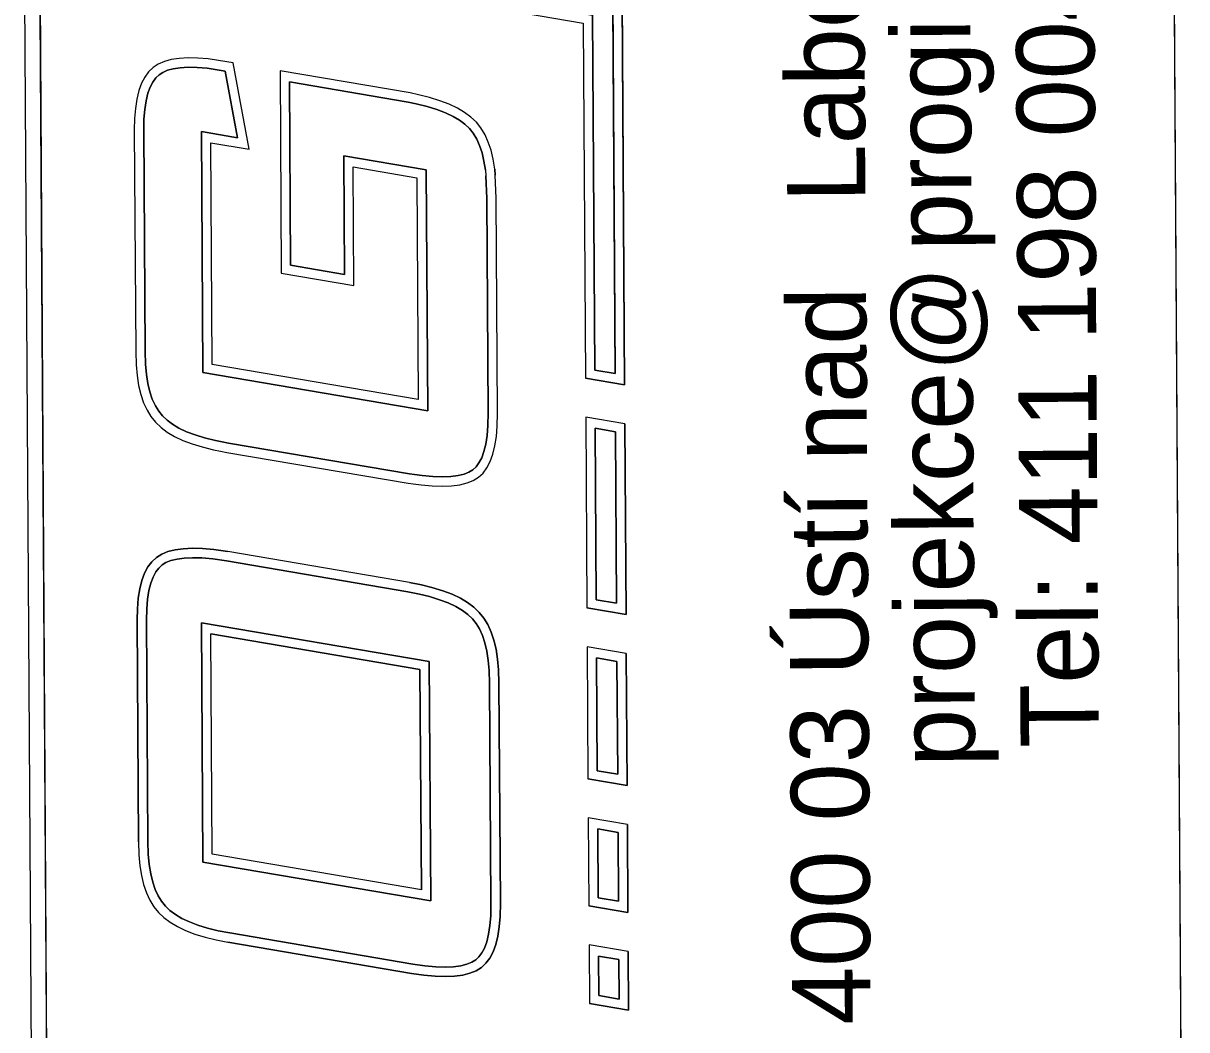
# Model space of a CAD drawing. Extents: x -735036 to -734743, y -1144813 to -1144181.
# Drawn here: x -734819.2 to -734790.93, y -1144221.87 to -1144197.41 of the extents above; entities that cross this region are included whole.
import ezdxf

# ---------------------------------------------------------------- set-up
doc = ezdxf.new("R2010")
doc.units = 0
doc.layers.add('000_rozpiska', color=7, linetype='Continuous')

# ---------------------------------------------------------------- blocks, each defined once
blk = doc.blocks.new('A$C2B726605')
at = {"layer": '000_rozpiska'}
for p, q in [((-8.894, 71.716), (-181.794, 71.716)), ((-8.894, 71.716), (-181.794, 71.716)), ((-8.894, 71.336), (-63.044, 71.336)), ((-23.113, 69), (-23.336, 68.949)), ((-22.876, 69.037), (-23.113, 69)), ((-22.611, 69.06), (-22.876, 69.037)), ((-22.293, 69.067), (-22.611, 69.06)), ((-16.9, 69.067), (-22.293, 69.067)), ((-16.631, 69.06), (-16.9, 69.067)), ((-16.382, 69.039), (-16.631, 69.06)), ((-16.158, 69.003), (-16.382, 69.039)), ((-15.946, 68.95), (-16.158, 69.003)), ((-35.366, 68.674), (-35.185, 68.734)), ((-35.185, 68.734), (-34.983, 68.781)), ((-34.983, 68.781), (-34.759, 68.816)), ((-34.759, 68.816), (-34.511, 68.836)), ((-34.511, 68.836), (-34.202, 68.844)), ((-34.202, 68.844), (-28.821, 68.844)), ((-28.821, 68.844), (-28.555, 68.837)), ((-28.555, 68.837), (-28.314, 68.816)), ((-28.314, 68.816), (-28.102, 68.782)), ((-28.102, 68.782), (-27.922, 68.735)), ((-27.922, 68.735), (-27.774, 68.68)), ((-23.875, 68.705), (-24.014, 68.594)), ((-23.718, 68.8), (-23.875, 68.705)), ((-23.536, 68.882), (-23.718, 68.8)), ((-23.336, 68.949), (-23.536, 68.882)), ((-23.274, 68.729), (-23.453, 68.67)), ((-23.07, 68.776), (-23.274, 68.729)), ((-22.849, 68.811), (-23.07, 68.776)), ((-22.599, 68.832), (-22.849, 68.811)), ((-22.29, 68.839), (-22.599, 68.832)), ((-16.903, 68.839), (-22.29, 68.839)), ((-16.644, 68.832), (-16.903, 68.839)), ((-16.41, 68.812), (-16.644, 68.832)), ((-16.203, 68.779), (-16.41, 68.812)), ((-16.014, 68.732), (-16.203, 68.779)), ((-15.868, 68.677), (-16.014, 68.732)), ((-15.774, 68.885), (-15.946, 68.95)), ((-15.623, 68.805), (-15.774, 68.885)), ((-15.494, 68.711), (-15.623, 68.805)), ((-15.389, 68.598), (-15.494, 68.711)), ((-35.877, 68.32), (-35.774, 68.43)), ((-35.774, 68.43), (-35.655, 68.523)), ((-35.655, 68.523), (-35.523, 68.603)), ((-35.523, 68.603), (-35.366, 68.674)), ((-27.774, 68.68), (-27.647, 68.612)), ((-27.647, 68.612), (-27.556, 68.541)), ((-27.556, 68.541), (-27.482, 68.458)), ((-27.482, 68.458), (-27.424, 68.363)), ((-24.14, 68.463), (-24.252, 68.312)), ((-24.014, 68.594), (-24.14, 68.463)), ((-23.86, 68.425), (-23.966, 68.315)), ((-23.744, 68.517), (-23.86, 68.425)), ((-23.612, 68.597), (-23.744, 68.517)), ((-23.453, 68.67), (-23.612, 68.597)), ((-15.744, 68.612), (-15.868, 68.677)), ((-15.646, 68.54), (-15.744, 68.612)), ((-15.57, 68.458), (-15.646, 68.54)), ((-15.513, 68.368), (-15.57, 68.458)), ((-15.31, 68.474), (-15.389, 68.598)), ((-15.247, 68.325), (-15.31, 68.474)), ((-36.072, 68.03), (-35.977, 68.188)), ((-35.977, 68.188), (-35.877, 68.32)), ((-27.424, 68.363), (-27.377, 68.245)), ((-27.377, 68.245), (-27.339, 68.093)), ((-24.358, 68.136), (-24.456, 67.934)), ((-24.252, 68.312), (-24.358, 68.136)), ((-24.062, 68.185), (-24.157, 68.028)), ((-23.966, 68.315), (-24.062, 68.185)), ((-15.462, 68.25), (-15.513, 68.368)), ((-15.425, 68.113), (-15.462, 68.25)), ((-15.201, 68.16), (-15.247, 68.325)), ((-15.174, 67.968), (-15.201, 68.16)), ((-36.24, 67.64), (-36.158, 67.849)), ((-36.158, 67.849), (-36.072, 68.03)), ((-27.339, 68.093), (-27.316, 67.921)), ((-27.316, 67.921), (-27.309, 67.715)), ((-24.456, 67.934), (-24.542, 67.709)), ((-24.247, 67.843), (-24.327, 67.634)), ((-24.157, 68.028), (-24.247, 67.843)), ((-15.401, 67.946), (-15.425, 68.113)), ((-15.39, 67.746), (-15.401, 67.946)), ((-15.161, 67.749), (-15.174, 67.968)), ((-36.313, 67.406), (-36.24, 67.64)), ((-27.309, 67.715), (-27.318, 67.49)), ((-24.542, 67.709), (-24.617, 67.47)), ((-24.327, 67.634), (-24.398, 67.408)), ((-15.396, 67.53), (-15.39, 67.746)), ((-15.168, 67.516), (-15.161, 67.749)), ((-36.377, 67.15), (-36.313, 67.406)), ((-35.686, 61.98), (-34.711, 67.51)), ((-35.414, 62.208), (-34.52, 67.282)), ((-34.711, 67.51), (-28.895, 67.51)), ((-34.52, 67.282), (-29.166, 67.282)), ((-30.06, 62.208), (-29.166, 67.282)), ((-29.869, 61.98), (-28.895, 67.51)), ((-27.318, 67.49), (-27.343, 67.228)), ((-24.617, 67.47), (-24.689, 67.189)), ((-24.398, 67.408), (-24.466, 67.138)), ((-23.773, 61.981), (-22.812, 67.436)), ((-22.812, 67.436), (-16.956, 67.436)), ((-16.956, 67.436), (-17.109, 66.562)), ((-15.455, 67.047), (-15.418, 67.292)), ((-15.418, 67.292), (-15.396, 67.53)), ((-15.192, 67.265), (-15.168, 67.516)), ((-36.434, 66.871), (-36.377, 67.15)), ((-27.343, 67.228), (-27.394, 66.891)), ((-24.723, 67.024), (-24.755, 66.868)), ((-24.689, 67.189), (-24.723, 67.024)), ((-24.466, 67.138), (-24.499, 66.978)), ((-23.501, 62.209), (-22.62, 67.208)), ((-22.62, 67.208), (-17.227, 67.208)), ((-17.227, 67.208), (-17.39, 66.281)), ((-15.489, 66.851), (-15.455, 67.047)), ((-15.293, 66.654), (-15.23, 67.01)), ((-15.23, 67.01), (-15.192, 67.265)), ((-37.443, 62.463), (-36.658, 66.917)), ((-37.218, 62.426), (-36.434, 66.871)), ((-27.394, 66.891), (-28.17, 62.485)), ((-27.946, 62.446), (-27.168, 66.857)), ((-24.755, 66.868), (-25.53, 62.465)), ((-24.531, 66.825), (-25.305, 62.43)), ((-24.499, 66.978), (-24.531, 66.825)), ((-17.109, 66.562), (-15.489, 66.851)), ((-17.39, 66.281), (-15.293, 66.654)), ((-20.41, 65.519), (-20.721, 63.755)), ((-15.492, 65.519), (-20.41, 65.519)), ((-16.049, 62.363), (-15.492, 65.519)), ((-20.219, 65.291), (-20.45, 63.983)), ((-15.764, 65.291), (-20.219, 65.291)), ((-16.272, 62.408), (-15.764, 65.291)), ((-20.45, 63.983), (-17.564, 63.983)), ((-17.564, 63.983), (-17.916, 61.981)), ((-20.721, 63.755), (-17.836, 63.755)), ((-17.836, 63.755), (-18.108, 62.209)), ((-28.168, 62.494), (-28.229, 62.211)), ((-37.262, 62.134), (-37.218, 62.426)), ((-35.414, 62.208), (-30.06, 62.208)), ((-28.229, 62.211), (-28.289, 61.967)), ((-25.547, 62.345), (-25.574, 62.154)), ((-25.53, 62.465), (-25.547, 62.345)), ((-25.321, 62.313), (-25.348, 62.126)), ((-25.305, 62.43), (-25.321, 62.313)), ((-18.108, 62.209), (-23.501, 62.209)), ((-16.383, 61.95), (-16.316, 62.214)), ((-16.316, 62.214), (-16.272, 62.408)), ((-16.095, 62.161), (-16.049, 62.363)), ((-37.288, 61.87), (-37.262, 62.134)), ((-35.686, 61.98), (-29.869, 61.98)), ((-28.289, 61.967), (-28.367, 61.72)), ((-25.574, 62.154), (-25.602, 61.884)), ((-25.348, 62.126), (-25.375, 61.868)), ((-17.916, 61.981), (-23.773, 61.981)), ((-16.456, 61.717), (-16.383, 61.95)), ((-16.163, 61.888), (-16.095, 62.161)), ((-37.298, 61.64), (-37.288, 61.87)), ((-37.291, 61.435), (-37.298, 61.64)), ((-28.367, 61.72), (-28.448, 61.51)), ((-25.602, 61.884), (-25.612, 61.64)), ((-25.612, 61.64), (-25.605, 61.413)), ((-25.375, 61.868), (-25.384, 61.64)), ((-25.384, 61.64), (-25.377, 61.431)), ((-16.537, 61.505), (-16.456, 61.717)), ((-16.328, 61.415), (-16.241, 61.642)), ((-16.241, 61.642), (-16.163, 61.888)), ((-37.268, 61.258), (-37.291, 61.435)), ((-28.448, 61.51), (-28.537, 61.326)), ((-25.605, 61.413), (-25.579, 61.21)), ((-25.377, 61.431), (-25.354, 61.252)), ((-16.626, 61.321), (-16.537, 61.505)), ((-16.426, 61.212), (-16.328, 61.415)), ((-37.231, 61.111), (-37.268, 61.258)), ((-37.184, 60.99), (-37.231, 61.111)), ((-28.63, 61.17), (-28.729, 61.038)), ((-28.537, 61.326), (-28.63, 61.17)), ((-25.579, 61.21), (-25.534, 61.032)), ((-25.354, 61.252), (-25.317, 61.102)), ((-25.317, 61.102), (-25.272, 60.989)), ((-16.816, 61.036), (-16.719, 61.167)), ((-16.719, 61.167), (-16.626, 61.321)), ((-16.53, 61.04), (-16.426, 61.212)), ((-37.126, 60.896), (-37.184, 60.99)), ((-37.055, 60.819), (-37.126, 60.896)), ((-36.959, 60.747), (-37.055, 60.819)), ((-28.949, 60.838), (-29.082, 60.76)), ((-28.835, 60.928), (-28.949, 60.838)), ((-28.729, 61.038), (-28.835, 60.928)), ((-25.534, 61.032), (-25.477, 60.887)), ((-25.477, 60.887), (-25.396, 60.755)), ((-25.272, 60.989), (-25.213, 60.893)), ((-25.213, 60.893), (-25.141, 60.813)), ((-25.141, 60.813), (-25.047, 60.744)), ((-17.18, 60.751), (-17.039, 60.833)), ((-17.039, 60.833), (-16.924, 60.924)), ((-16.924, 60.924), (-16.816, 61.036)), ((-16.771, 60.755), (-16.642, 60.889)), ((-16.642, 60.889), (-16.53, 61.04)), ((-36.839, 60.683), (-36.959, 60.747)), ((-36.687, 60.627), (-36.839, 60.683)), ((-36.506, 60.581), (-36.687, 60.627)), ((-36.295, 60.547), (-36.506, 60.581)), ((-36.059, 60.526), (-36.295, 60.547)), ((-35.746, 60.519), (-36.059, 60.526)), ((-30.401, 60.519), (-35.746, 60.519)), ((-30.095, 60.527), (-30.401, 60.519)), ((-29.849, 60.547), (-30.095, 60.527)), ((-29.624, 60.582), (-29.849, 60.547)), ((-29.421, 60.629), (-29.624, 60.582)), ((-29.242, 60.688), (-29.421, 60.629)), ((-29.082, 60.76), (-29.242, 60.688)), ((-25.396, 60.755), (-25.295, 60.643)), ((-25.295, 60.643), (-25.168, 60.55)), ((-25.168, 60.55), (-25.016, 60.469)), ((-25.047, 60.744), (-24.922, 60.677)), ((-24.922, 60.677), (-24.774, 60.621)), ((-24.774, 60.621), (-24.592, 60.576)), ((-24.592, 60.576), (-24.381, 60.543)), ((-24.381, 60.543), (-24.143, 60.522)), ((-24.143, 60.522), (-23.837, 60.515)), ((-23.837, 60.515), (-18.622, 60.515)), ((-18.622, 60.515), (-18.073, 60.532)), ((-17.938, 60.543), (-18.073, 60.532)), ((-17.938, 60.543), (-17.714, 60.577)), ((-17.714, 60.577), (-17.514, 60.623)), ((-17.514, 60.623), (-17.334, 60.683)), ((-17.334, 60.683), (-17.18, 60.751)), ((-17.252, 60.47), (-17.076, 60.547)), ((-17.076, 60.547), (-16.91, 60.645)), ((-16.91, 60.645), (-16.771, 60.755)), ((-25.016, 60.469), (-24.842, 60.403)), ((-24.842, 60.403), (-24.638, 60.353)), ((-24.638, 60.353), (-24.409, 60.316)), ((-24.409, 60.316), (-24.156, 60.295)), ((-24.156, 60.295), (-23.84, 60.287)), ((-23.84, 60.287), (-18.618, 60.287)), ((-18.618, 60.287), (-18.06, 60.305)), ((-17.912, 60.316), (-18.06, 60.305)), ((-17.912, 60.316), (-17.671, 60.353)), ((-17.671, 60.353), (-17.453, 60.403)), ((-17.453, 60.403), (-17.252, 60.47)), ((-38.371, 57.193), (-38.204, 58.143)), ((-36.779, 58.143), (-38.204, 58.143)), ((-36.946, 57.193), (-36.779, 58.143)), ((-35.996, 57.193), (-35.829, 58.143)), ((-33.691, 58.143), (-35.829, 58.143)), ((-33.859, 57.193), (-33.691, 58.143)), ((-32.909, 57.193), (-32.741, 58.143)), ((-29.535, 58.143), (-32.741, 58.143)), ((-29.702, 57.193), (-29.535, 58.143)), ((-28.752, 57.193), (-28.585, 58.143)), ((-23.954, 58.143), (-28.585, 58.143)), ((-24.121, 57.193), (-23.954, 58.143)), ((-23.171, 57.193), (-23.004, 58.143)), ((-14.38, 58.143), (-23.004, 58.143)), ((-38.099, 57.421), (-38.012, 57.915)), ((-37.05, 57.915), (-38.012, 57.915)), ((-37.137, 57.421), (-37.05, 57.915)), ((-35.724, 57.421), (-35.637, 57.915)), ((-33.963, 57.915), (-35.637, 57.915)), ((-34.05, 57.421), (-33.963, 57.915)), ((-32.637, 57.421), (-32.55, 57.915)), ((-29.807, 57.915), (-32.55, 57.915)), ((-29.894, 57.421), (-29.807, 57.915)), ((-28.481, 57.421), (-28.393, 57.915)), ((-24.225, 57.915), (-28.393, 57.915)), ((-24.312, 57.421), (-24.225, 57.915)), ((-22.899, 57.421), (-22.812, 57.915)), ((-14.189, 57.915), (-22.812, 57.915)), ((-37.137, 57.421), (-38.099, 57.421)), ((-34.05, 57.421), (-35.724, 57.421)), ((-29.894, 57.421), (-32.637, 57.421)), ((-24.312, 57.421), (-28.481, 57.421)), ((-12.666, 57.421), (-22.899, 57.421)), ((-36.946, 57.193), (-38.371, 57.193)), ((-33.859, 57.193), (-35.996, 57.193)), ((-29.702, 57.193), (-32.909, 57.193)), ((-24.121, 57.193), (-28.752, 57.193)), ((-12.474, 57.193), (-23.171, 57.193)), ((-6.424, 43.784), (-63.044, 43.784))]:
    blk.add_line(p, q, dxfattribs=at)
for points in [[(-63.044, 43.784), (-63.044, 71.336), (-8.894, 71.336)], [(-28.055, 69.005), (-28.286, 69.042), (-28.542, 69.065), (-28.815, 69.072), (-34.205, 69.072), (-34.524, 69.064), (-34.786, 69.043), (-35.027, 69.005), (-35.246, 68.954), (-35.449, 68.887), (-35.629, 68.805), (-35.786, 68.711), (-35.928, 68.598), (-36.052, 68.467), (-36.166, 68.316), (-36.273, 68.138), (-36.368, 67.94), (-36.455, 67.716), (-36.532, 67.468), (-36.599, 67.2), (-36.658, 66.917), (-37.443, 62.463), (-37.489, 62.162), (-37.516, 61.886), (-37.526, 61.641), (-37.518, 61.417), (-37.493, 61.216), (-37.449, 61.041), (-37.388, 60.887), (-37.309, 60.758), (-37.209, 60.649), (-37.082, 60.554), (-36.933, 60.474), (-36.755, 60.409), (-36.552, 60.357), (-36.323, 60.321), (-36.071, 60.299), (-35.752, 60.291), (-30.398, 60.291), (-30.083, 60.299), (-29.822, 60.321), (-29.581, 60.358), (-29.359, 60.41), (-29.16, 60.475), (-28.977, 60.557), (-28.82, 60.65), (-28.682, 60.759), (-28.555, 60.89), (-28.441, 61.042), (-28.336, 61.217), (-28.238, 61.419), (-28.152, 61.644), (-28.07, 61.905), (-28.007, 62.16), (-27.946, 62.446), (-27.168, 66.857), (-27.117, 67.2), (-27.09, 67.475), (-27.081, 67.715), (-27.089, 67.94), (-27.115, 68.135), (-27.159, 68.315), (-27.219, 68.465), (-27.298, 68.595), (-27.4, 68.709), (-27.523, 68.804), (-27.68, 68.888), (-27.853, 68.953), (-28.055, 69.005)], [(-34.205, 69.072), (-34.524, 69.064), (-34.786, 69.043), (-35.027, 69.005), (-35.246, 68.954), (-35.449, 68.887), (-35.629, 68.805), (-35.786, 68.711), (-35.928, 68.598), (-36.052, 68.467), (-36.166, 68.316), (-36.273, 68.138), (-36.368, 67.94), (-36.455, 67.716), (-36.532, 67.468), (-36.599, 67.2), (-36.658, 66.917)], [(-34.205, 69.072), (-28.815, 69.072), (-28.542, 69.065), (-28.286, 69.042), (-28.055, 69.005), (-27.853, 68.953), (-27.68, 68.888), (-27.523, 68.804), (-27.4, 68.709), (-27.298, 68.595), (-27.219, 68.465), (-27.159, 68.315), (-27.115, 68.135), (-27.089, 67.94), (-27.081, 67.715), (-27.09, 67.475), (-27.117, 67.2), (-27.168, 66.857)], [(-15.946, 68.95), (-16.158, 69.003), (-16.382, 69.039), (-16.631, 69.06), (-16.9, 69.067), (-22.293, 69.067), (-22.611, 69.06), (-22.876, 69.037), (-23.113, 69), (-23.336, 68.949), (-23.536, 68.882), (-23.718, 68.8), (-23.875, 68.705), (-24.014, 68.594), (-24.14, 68.463), (-24.252, 68.312), (-24.358, 68.136), (-24.456, 67.934), (-24.542, 67.709), (-24.617, 67.47), (-24.689, 67.189), (-24.723, 67.024), (-24.755, 66.868), (-25.53, 62.465), (-25.547, 62.345), (-25.574, 62.154), (-25.602, 61.884), (-25.612, 61.64), (-25.605, 61.413), (-25.579, 61.21), (-25.534, 61.032), (-25.477, 60.887), (-25.396, 60.755), (-25.295, 60.643), (-25.168, 60.55), (-25.016, 60.469), (-24.842, 60.403), (-24.638, 60.353), (-24.409, 60.316), (-24.156, 60.295), (-23.84, 60.287), (-18.618, 60.287), (-18.06, 60.305), (-17.912, 60.316), (-17.671, 60.353), (-17.453, 60.403), (-17.252, 60.47), (-17.076, 60.547), (-16.91, 60.645), (-16.771, 60.755), (-16.642, 60.889), (-16.53, 61.04), (-16.426, 61.212), (-16.328, 61.415), (-16.241, 61.642), (-16.163, 61.888), (-16.095, 62.161), (-16.049, 62.363), (-15.492, 65.519), (-20.41, 65.519), (-20.721, 63.755), (-17.836, 63.755), (-18.108, 62.209), (-23.501, 62.209), (-22.62, 67.208), (-17.227, 67.208), (-17.39, 66.281), (-15.293, 66.654), (-15.23, 67.01), (-15.192, 67.265), (-15.168, 67.516), (-15.161, 67.749), (-15.174, 67.968), (-15.201, 68.16), (-15.247, 68.325), (-15.31, 68.474), (-15.389, 68.598), (-15.494, 68.711), (-15.623, 68.805), (-15.774, 68.885), (-15.946, 68.95)], [(-6.424, 68.866), (-6.424, 43.784), (-63.044, 43.784)], [(-27.309, 67.715), (-27.316, 67.921), (-27.339, 68.093), (-27.377, 68.245), (-27.424, 68.363), (-27.482, 68.458), (-27.556, 68.541), (-27.647, 68.612), (-27.774, 68.68), (-27.922, 68.735), (-28.102, 68.782), (-28.314, 68.816), (-28.555, 68.837), (-28.821, 68.844), (-34.202, 68.844), (-34.511, 68.836), (-34.759, 68.816), (-34.983, 68.781), (-35.185, 68.734), (-35.366, 68.674), (-35.523, 68.603), (-35.655, 68.523), (-35.774, 68.43), (-35.877, 68.32), (-35.977, 68.188), (-36.072, 68.03), (-36.158, 67.849), (-36.24, 67.64), (-36.313, 67.406), (-36.377, 67.15), (-36.434, 66.871), (-37.218, 62.426), (-37.262, 62.134), (-37.288, 61.87), (-37.298, 61.64), (-37.291, 61.435), (-37.268, 61.258), (-37.231, 61.111), (-37.184, 60.99), (-37.126, 60.896), (-37.055, 60.819), (-36.959, 60.747), (-36.839, 60.683), (-36.687, 60.627), (-36.506, 60.581), (-36.295, 60.547), (-36.059, 60.526), (-35.746, 60.519), (-30.401, 60.519), (-30.095, 60.527), (-29.849, 60.547), (-29.624, 60.582), (-29.421, 60.629), (-29.242, 60.688), (-29.082, 60.76), (-28.949, 60.838), (-28.835, 60.928), (-28.729, 61.038), (-28.63, 61.17), (-28.537, 61.326), (-28.448, 61.51), (-28.367, 61.72), (-28.289, 61.967), (-28.229, 62.211), (-28.169, 62.489), (-27.394, 66.891), (-27.343, 67.228), (-27.318, 67.49), (-27.309, 67.715)], [(-28.821, 68.844), (-28.555, 68.837), (-28.314, 68.816), (-28.102, 68.782), (-27.922, 68.735), (-27.774, 68.68), (-27.647, 68.612), (-27.556, 68.541), (-27.482, 68.458), (-27.424, 68.363), (-27.377, 68.245), (-27.339, 68.093), (-27.316, 67.921), (-27.309, 67.715), (-27.318, 67.49), (-27.343, 67.228), (-27.394, 66.891), (-28.169, 62.489), (-28.229, 62.211), (-28.289, 61.967), (-28.367, 61.72), (-28.448, 61.51), (-28.537, 61.326), (-28.63, 61.17), (-28.729, 61.038), (-28.835, 60.928), (-28.949, 60.838), (-29.082, 60.76), (-29.242, 60.688), (-29.421, 60.629), (-29.624, 60.582), (-29.849, 60.547), (-30.095, 60.527), (-30.401, 60.519), (-35.746, 60.519), (-36.059, 60.526), (-36.295, 60.547), (-36.506, 60.581), (-36.687, 60.627), (-36.839, 60.683), (-36.959, 60.747), (-37.055, 60.819), (-37.126, 60.896), (-37.184, 60.99), (-37.231, 61.111), (-37.268, 61.258), (-37.291, 61.435), (-37.298, 61.64), (-37.288, 61.87), (-37.262, 62.134), (-37.218, 62.426), (-36.434, 66.871), (-36.377, 67.15), (-36.313, 67.406), (-36.24, 67.64), (-36.158, 67.849), (-36.072, 68.03), (-35.977, 68.188), (-35.877, 68.32), (-35.774, 68.43), (-35.655, 68.523), (-35.523, 68.603), (-35.366, 68.674), (-35.185, 68.734), (-34.983, 68.781), (-34.759, 68.816), (-34.511, 68.836), (-34.202, 68.844), (-28.821, 68.844)], [(-16.903, 68.839), (-16.644, 68.832), (-16.41, 68.812), (-16.203, 68.779), (-16.014, 68.732), (-15.868, 68.677), (-15.744, 68.612), (-15.646, 68.54), (-15.57, 68.458), (-15.513, 68.368), (-15.462, 68.25), (-15.425, 68.113), (-15.401, 67.946), (-15.39, 67.746), (-15.396, 67.53), (-15.418, 67.292), (-15.455, 67.047), (-15.489, 66.851), (-17.109, 66.562), (-16.956, 67.436), (-22.812, 67.436), (-23.773, 61.981), (-17.916, 61.981), (-17.564, 63.983), (-20.45, 63.983), (-20.219, 65.291), (-15.764, 65.291), (-16.272, 62.408), (-16.316, 62.214), (-16.383, 61.95), (-16.456, 61.717), (-16.537, 61.505), (-16.626, 61.321), (-16.719, 61.167), (-16.816, 61.036), (-16.924, 60.924), (-17.039, 60.833), (-17.18, 60.751), (-17.334, 60.683), (-17.514, 60.623), (-17.714, 60.577), (-17.938, 60.543), (-18.073, 60.532), (-18.622, 60.515), (-23.837, 60.515), (-24.143, 60.522), (-24.381, 60.543), (-24.592, 60.576), (-24.774, 60.621), (-24.922, 60.677), (-25.047, 60.744), (-25.141, 60.813), (-25.213, 60.893), (-25.272, 60.989), (-25.317, 61.102), (-25.354, 61.252), (-25.377, 61.431), (-25.384, 61.64), (-25.375, 61.868), (-25.348, 62.126), (-25.321, 62.313), (-25.305, 62.43), (-24.531, 66.825), (-24.499, 66.978), (-24.466, 67.138), (-24.398, 67.408), (-24.327, 67.634), (-24.247, 67.843), (-24.157, 68.028), (-24.062, 68.185), (-23.966, 68.315), (-23.86, 68.425), (-23.744, 68.517), (-23.612, 68.597), (-23.453, 68.67), (-23.274, 68.729), (-23.07, 68.776), (-22.849, 68.811), (-22.599, 68.832), (-22.29, 68.839), (-16.903, 68.839)], [(-28.895, 67.51), (-29.869, 61.98), (-35.686, 61.98), (-34.711, 67.51), (-28.895, 67.51)], [(-28.895, 67.51), (-34.711, 67.51), (-35.686, 61.98), (-29.869, 61.98), (-28.895, 67.51)], [(-29.166, 67.282), (-30.06, 62.208), (-35.414, 62.208), (-34.52, 67.282), (-29.166, 67.282)], [(-35.752, 60.291), (-36.071, 60.299), (-36.323, 60.321), (-36.552, 60.357), (-36.755, 60.409), (-36.933, 60.474), (-37.082, 60.554), (-37.209, 60.649), (-37.309, 60.758), (-37.388, 60.887), (-37.449, 61.041), (-37.493, 61.216), (-37.518, 61.417), (-37.526, 61.641), (-37.516, 61.886), (-37.489, 62.162), (-37.443, 62.463)], [(-27.946, 62.446), (-28.007, 62.16), (-28.07, 61.905), (-28.152, 61.644), (-28.238, 61.419), (-28.336, 61.217), (-28.441, 61.042), (-28.555, 60.89), (-28.682, 60.759), (-28.82, 60.65), (-28.977, 60.557), (-29.16, 60.475), (-29.359, 60.41), (-29.581, 60.358), (-29.822, 60.321), (-30.083, 60.299), (-30.398, 60.291), (-35.752, 60.291)], [(-12.055, 59.574), (-14.128, 59.574), (-14.38, 58.143), (-23.004, 58.143), (-23.171, 57.193), (-12.474, 57.193), (-12.055, 59.574)], [(-12.326, 59.346), (-12.666, 57.421), (-22.899, 57.421), (-22.812, 57.915), (-14.189, 57.915), (-13.937, 59.346), (-12.326, 59.346)], [(-12.326, 59.346), (-13.937, 59.346), (-14.189, 57.915), (-22.812, 57.915), (-22.899, 57.421), (-12.666, 57.421), (-12.326, 59.346)], [(-36.779, 58.143), (-38.204, 58.143), (-38.371, 57.193), (-36.946, 57.193), (-36.779, 58.143)], [(-33.691, 58.143), (-35.829, 58.143), (-35.996, 57.193), (-33.859, 57.193), (-33.691, 58.143)], [(-29.535, 58.143), (-32.741, 58.143), (-32.909, 57.193), (-29.702, 57.193), (-29.535, 58.143)], [(-23.954, 58.143), (-28.585, 58.143), (-28.752, 57.193), (-24.121, 57.193), (-23.954, 58.143)], [(-37.05, 57.915), (-37.137, 57.421), (-38.099, 57.421), (-38.012, 57.915), (-37.05, 57.915)], [(-37.05, 57.915), (-38.012, 57.915), (-38.099, 57.421), (-37.137, 57.421), (-37.05, 57.915)], [(-33.963, 57.915), (-34.05, 57.421), (-35.724, 57.421), (-35.637, 57.915), (-33.963, 57.915)], [(-33.963, 57.915), (-35.637, 57.915), (-35.724, 57.421), (-34.05, 57.421), (-33.963, 57.915)], [(-29.807, 57.915), (-29.894, 57.421), (-32.637, 57.421), (-32.55, 57.915), (-29.807, 57.915)], [(-29.807, 57.915), (-32.55, 57.915), (-32.637, 57.421), (-29.894, 57.421), (-29.807, 57.915)], [(-24.225, 57.915), (-24.312, 57.421), (-28.481, 57.421), (-28.393, 57.915), (-24.225, 57.915)], [(-24.225, 57.915), (-28.393, 57.915), (-28.481, 57.421), (-24.312, 57.421), (-24.225, 57.915)]]:
    blk.add_lwpolyline(points, dxfattribs=at)
for s, p in [('400 03 Ústí nad', (-38.76, 51.316)), ('Labem', (-18.775, 51.316)), ('projekce@', (-32.507, 48.739)), ('progi', (-19.971, 48.739)), ('Tel: 411 198 004', (-32.058, 45.729))]:
    blk.add_text(s, height=1.9, dxfattribs=at).set_placement(p)

msp = doc.modelspace()

# ---------------------------------------------------------------- block references
at = {"layer": '000_rozpiska', "rotation": 90.35414249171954}
msp.add_blockref('A$C2B726605', (-734747.538, -1144182.67), dxfattribs=at)

doc.saveas('drawing.dxf')
